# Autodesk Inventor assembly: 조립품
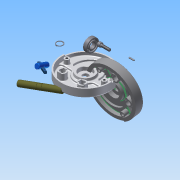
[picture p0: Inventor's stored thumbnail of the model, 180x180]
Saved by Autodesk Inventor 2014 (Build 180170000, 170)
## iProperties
Created: 2015-04
Part Number: 조립품
Document SubType Name: Assembly
Designer: Administrator
Author: Administrator
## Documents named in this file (10)
- C:\Documents and Settings\Administrator\바탕 화면\450405v1021\조립품.iam
- C:\Documents and Settings\Administrator\바탕 화면\450405v1021\덮개.ipt
- C:\Documents and Settings\Administrator\바탕 화면\450405v1021\멈춤링.ipt
- C:\Documents and Settings\Administrator\바탕 화면\450405v1021\베어링62_22.ipt
- C:\Documents and Settings\Administrator\바탕 화면\450405v1021\본체.ipt
- C:\Documents and Settings\Administrator\바탕 화면\450405v1021\슬라이더2.ipt
- C:\Documents and Settings\Administrator\바탕 화면\450405v1021\슬라이더.ipt
- C:\Documents and Settings\Administrator\바탕 화면\450405v1021\축.ipt
- C:\Documents and Settings\Administrator\바탕 화면\450405v1021\평행핀.ipt
- C:\Documents and Settings\Administrator\바탕 화면\450405v1021\M 10 x 35.ipt
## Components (1 placed, 1 different names)
1. M 10 x 35:1
